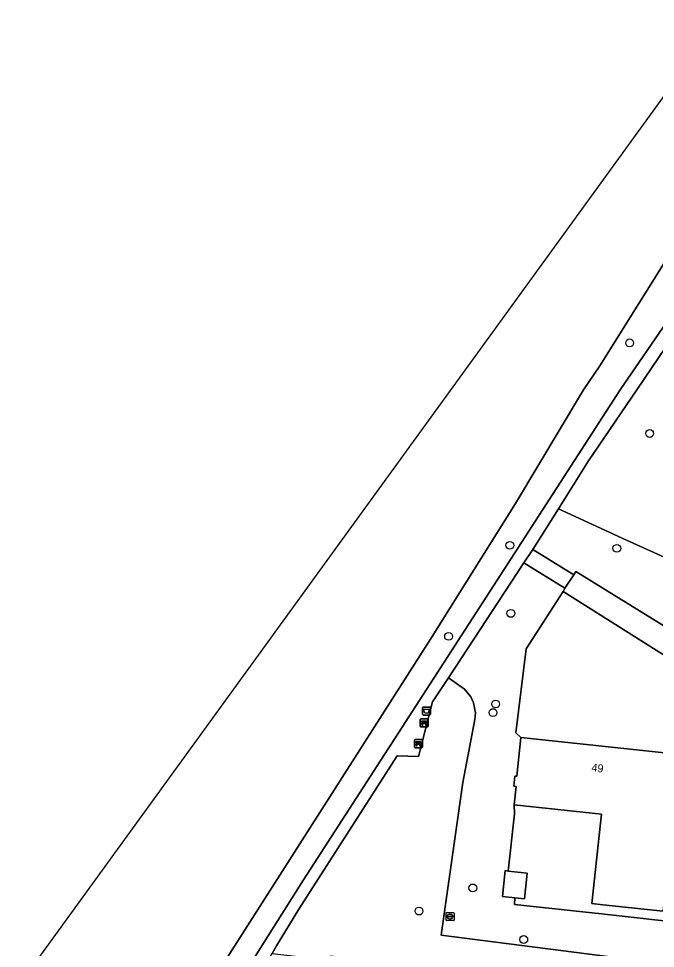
# Model space of a CAD drawing. Extents: x 162396 to 163643, y 386452 to 387406.
# Drawn here: x 162747.7 to 162827.2, y 386930.2 to 387046.4 of the extents above; entities that cross this region are included whole.
import ezdxf

# ---------------------------------------------------------------- set-up
doc = ezdxf.new("R2010")
doc.units = 0
for name, color, linetype in [('IMGEO_Afvalbak', 7, 'Continuous'), ('IMGEO_Bank', 7, 'Continuous'), ('IMGEO_Boom', 7, 'Continuous'), ('IMGEO_Erf', 7, 'Continuous'), ('IMGEO_Groenvoorziening', 7, 'Continuous'), ('IMGEO_Meer_plas_ven_vijver', 7, 'Continuous'), ('IMGEO_Pand', 7, 'Continuous'), ('IMGEO_Pand_nummerreeks', 7, 'Continuous'), ('IMGEO_Rioolput', 7, 'Continuous'), ('IMGEO_Voetpad_halfverhard', 7, 'Continuous'), ('IMGEO_Voetpad_open', 7, 'Continuous')]:
    doc.layers.add(name, color=color, linetype=linetype)

msp = doc.modelspace()

# ---------------------------------------------------------------- linework, layer by layer
at = {"layer": 'IMGEO_Afvalbak'}
for p, q in [((162798.12, 386959.5), (162798.12, 386960.3)), ((162798.12, 386960.3), (162798.12, 386959.5)), ((162798.22, 386960.4), (162799.01, 386960.4)), ((162799.01, 386960.4), (162798.22, 386960.4)), ((162799.11, 386960.3), (162799.11, 386959.5)), ((162799.11, 386959.5), (162799.11, 386960.3)), ((162799.01, 386959.4), (162798.22, 386959.4)), ((162798.22, 386959.4), (162799.01, 386959.4))]:
    msp.add_line(p, q, dxfattribs=at)
msp.add_lwpolyline([(162798.26, 386960.12), (162798.97, 386960.12), (162798.82, 386959.65), (162798.41, 386959.65), (162798.26, 386960.12)], dxfattribs=at)
for centre, start, end in [((162798.22, 386960.3), 90, 180), ((162798.22, 386960.3), 90, 180), ((162799.01, 386960.3), 0, 90), ((162799.01, 386960.3), 360, 90), ((162798.22, 386959.5), 180, 270), ((162798.22, 386959.5), 180, 270), ((162799.01, 386959.5), 270, 0), ((162799.01, 386959.5), 270, 0)]:
    msp.add_arc(centre, 0.1, start, end, dxfattribs=at)
at = {"layer": 'IMGEO_Bank'}
for p, q in [((162797.83, 386957.99), (162797.83, 386958.83)), ((162797.83, 386958.83), (162797.83, 386957.99)), ((162797.91, 386958.91), (162798.75, 386958.91)), ((162798.75, 386958.91), (162797.91, 386958.91)), ((162798.14, 386958.42), (162798.14, 386958.52)), ((162798.18, 386958.52), (162798.18, 386958.42)), ((162798.47, 386958.53), (162798.19, 386958.53)), ((162798.48, 386958.42), (162798.48, 386958.52)), ((162798.52, 386958.52), (162798.52, 386958.42)), ((162798.83, 386958.84), (162798.83, 386958)), ((162798.83, 386958), (162798.83, 386958.84)), ((162798.76, 386957.91), (162797.92, 386957.91)), ((162797.92, 386957.91), (162798.76, 386957.91)), ((162798.53, 386958.31), (162798.14, 386958.31)), ((162798.19, 386958.41), (162798.47, 386958.41)), ((162797.11, 386955.39), (162797.11, 386956.24)), ((162797.11, 386956.24), (162797.11, 386955.39)), ((162797.19, 386956.32), (162798.03, 386956.32)), ((162798.03, 386956.32), (162797.19, 386956.32)), ((162798.11, 386956.25), (162798.11, 386955.4)), ((162798.11, 386955.4), (162798.11, 386956.25)), ((162798.04, 386955.32), (162797.2, 386955.32)), ((162797.2, 386955.32), (162798.04, 386955.32)), ((162797.81, 386955.72), (162797.41, 386955.72)), ((162797.42, 386955.83), (162797.42, 386955.93)), ((162797.46, 386955.93), (162797.46, 386955.83)), ((162797.75, 386955.94), (162797.47, 386955.94)), ((162797.47, 386955.82), (162797.75, 386955.82)), ((162797.76, 386955.83), (162797.76, 386955.93)), ((162797.8, 386955.93), (162797.8, 386955.83))]:
    msp.add_line(p, q, dxfattribs=at)
for points in [[(162798.13, 386958.53), (162798.05, 386958.53), (162798.05, 386958.69), (162798.61, 386958.69), (162798.61, 386958.53), (162798.53, 386958.53)], [(162798.08, 386958.31), (162797.94, 386958.31), (162798.05, 386958.41), (162798.13, 386958.41)], [(162798.13, 386958.3), (162798.13, 386958.09), (162798.09, 386958.09), (162798.09, 386958.3)], [(162798.53, 386958.41), (162798.61, 386958.41), (162798.72, 386958.31), (162798.59, 386958.31)], [(162798.58, 386958.3), (162798.58, 386958.09), (162798.54, 386958.09), (162798.54, 386958.3)], [(162797.36, 386955.72), (162797.22, 386955.72), (162797.33, 386955.82), (162797.41, 386955.82)], [(162797.41, 386955.94), (162797.33, 386955.94), (162797.33, 386956.1), (162797.89, 386956.1), (162797.89, 386955.94), (162797.81, 386955.94)], [(162797.41, 386955.71), (162797.41, 386955.5), (162797.36, 386955.5), (162797.36, 386955.71)], [(162797.81, 386955.82), (162797.89, 386955.82), (162798, 386955.72), (162797.86, 386955.72)], [(162797.86, 386955.71), (162797.86, 386955.5), (162797.81, 386955.5), (162797.81, 386955.71)]]:
    msp.add_lwpolyline(points, dxfattribs=at)
for centre, radius, start, end in [((162797.91, 386958.83), 0.0779, 92.4484, 184.2845), ((162797.91, 386958.83), 0.0779, 92.4484, 184.2845), ((162798.13, 386958.52), 0.00671, 2.8957, 87.1043), ((162798.19, 386958.52), 0.00671, 92.8957, 177.1043), ((162798.47, 386958.52), 0.00671, 2.8957, 87.1043), ((162798.53, 386958.52), 0.00671, 92.8957, 177.1043), ((162798.75, 386958.83), 0.0779, 2.4484, 94.2845), ((162798.75, 386958.83), 0.0779, 2.4484, 94.2845), ((162797.91, 386957.99), 0.0779, 182.4484, 274.2845), ((162797.91, 386957.99), 0.0779, 182.4484, 274.2845), ((162798.08, 386958.3), 0.00671, 2.8957, 87.1043), ((162798.13, 386958.42), 0.00671, 272.8957, 357.1043), ((162798.14, 386958.3), 0.00671, 92.8957, 177.1043), ((162798.19, 386958.42), 0.00671, 182.8957, 267.1043), ((162798.47, 386958.42), 0.00671, 272.8957, 357.1043), ((162798.53, 386958.42), 0.00671, 182.8957, 267.1043), ((162798.53, 386958.3), 0.00671, 2.8957, 87.1043), ((162798.59, 386958.3), 0.00671, 92.8957, 177.1043), ((162798.75, 386957.99), 0.0779, 272.4484, 4.2845), ((162798.75, 386957.99), 0.0779, 272.4484, 4.2845), ((162797.19, 386956.24), 0.0779, 92.4484, 184.2845), ((162797.19, 386956.24), 0.0779, 92.4484, 184.2845), ((162798.03, 386956.24), 0.0779, 2.4484, 94.2845), ((162798.03, 386956.24), 0.0779, 2.4484, 94.2845), ((162797.19, 386955.4), 0.0779, 182.4484, 274.2845), ((162797.19, 386955.4), 0.0779, 182.4484, 274.2845), ((162797.36, 386955.71), 0.00671, 2.8957, 87.1043), ((162797.41, 386955.93), 0.00671, 2.8957, 87.1043), ((162797.41, 386955.83), 0.00671, 272.8957, 357.1043), ((162797.42, 386955.71), 0.00671, 92.8957, 177.1043), ((162797.47, 386955.93), 0.00671, 92.8957, 177.1043), ((162797.47, 386955.83), 0.00671, 182.8957, 267.1043), ((162797.75, 386955.93), 0.00671, 2.8957, 87.1043), ((162797.75, 386955.83), 0.00671, 272.8957, 357.1043), ((162797.81, 386955.93), 0.00671, 92.8957, 177.1043), ((162797.81, 386955.83), 0.00671, 182.8957, 267.1043), ((162797.81, 386955.71), 0.00671, 2.8957, 87.1043), ((162797.86, 386955.71), 0.00671, 92.8957, 177.1043), ((162798.03, 386955.4), 0.0779, 272.4484, 4.2845), ((162798.03, 386955.4), 0.0779, 272.4484, 4.2845)]:
    msp.add_arc(centre, radius, start, end, dxfattribs=at)
at = {"layer": 'IMGEO_Boom'}
for centre in [(162823.99, 387005.88), (162826.48, 386994.57), (162809.02, 386980.6), (162822.39, 386980.22), (162809.16, 386972.09), (162801.38, 386969.22), (162807.26, 386960.78), (162806.92, 386959.7), (162804.4, 386937.8), (162797.68, 386934.91), (162810.76, 386931.36)]:
    msp.add_circle(centre, 0.489, dxfattribs=at)
at = {"layer": 'IMGEO_Erf'}
for points in [[(162831.57, 386964.81), (162815.68, 386974.83), (162811.08, 386967.66), (162809.79, 386957.16), (162810.4, 386956.6), (162830.3, 386954.46)], [(162828.17, 386934.88), (162820.65, 386935.69), (162819.27, 386935.84), (162820.35, 386945.9), (162820.47, 386947.02), (162809.55, 386948.19), (162809.62, 386947.04), (162808.83, 386939.91), (162811.19, 386939.66), (162810.84, 386936.43), (162809.66, 386936.56), (162809.62, 386935.74), (162820.48, 386934.56), (162828.24, 386933.71)]]:
    msp.add_lwpolyline(points, dxfattribs=at)
at = {"layer": 'IMGEO_Groenvoorziening'}
for points in [[(162822.79, 387000), (162840.21, 387025.39), (162850.89, 387039.17), (162851.19, 387040.6), (162851.15, 387042.93), (162848.38, 387044.77), (162846.89, 387045.9), (162844.23, 387041.73), (162841.3, 387036.72), (162834.64, 387026.06), (162820.24, 387003), (162818.24, 387000.01), (162809.72, 386985.81), (162799.34, 386969.19), (162769.37, 386922.25), (162756.79, 386901.93), (162764.1, 386897.03), (162767.1, 386909.87), (162773.1, 386921.91), (162776.86, 386928.66), (162783.25, 386938.8)], [(162815.1, 386985.16), (162811.9, 386980.07), (162817.03, 386976.92), (162817.25, 386977.34), (162828.23, 386970.53), (162829.12, 386974.33), (162829.12, 386977.33), (162829.12, 386978.76), (162823.57, 386981.26)]]:
    msp.add_lwpolyline(points, close=True, dxfattribs=at)
for points in [[(162837.53, 387018.71), (162824.9, 387000), (162818.86, 386991.15), (162815.1, 386985.16), (162823.57, 386981.26), (162829.12, 386978.76)], [(162828.24, 386933.71), (162820.48, 386934.56), (162809.62, 386935.74), (162809.66, 386936.56), (162808.1, 386936.73), (162808.44, 386939.96), (162808.83, 386939.91), (162809.62, 386947.04), (162809.55, 386948.19), (162809.8, 386950.48), (162809.52, 386950.51), (162809.65, 386951.77), (162809.88, 386951.75), (162810.4, 386956.6), (162809.79, 386957.16), (162811.08, 386967.66), (162815.68, 386974.83), (162815.91, 386975.23), (162810.79, 386978.39), (162801.36, 386964.04), (162803.37, 386962.61), (162804.16, 386961.67), (162804.51, 386960.91), (162804.74, 386959.67), (162804.67, 386958.84), (162803.17, 386950.96), (162800.47, 386931.89), (162828.69, 386928.27)], [(162828.69, 386928.27), (162800.47, 386931.89), (162803.17, 386950.96), (162804.67, 386958.84), (162804.74, 386959.67), (162804.51, 386960.91), (162804.16, 386961.67), (162803.37, 386962.61), (162801.36, 386964.04), (162799.38, 386961.03), (162797.63, 386954.22), (162794.98, 386954.29), (162782.7, 386935.15), (162779.88, 386930.58), (162779.36, 386929.62), (162786.56, 386928.76), (162786.64, 386929.32), (162812.5, 386926.45), (162811.66, 386918.95), (162813.64, 386916.29), (162827.93, 386914.73)]]:
    msp.add_lwpolyline(points, dxfattribs=at)
at = {"layer": 'IMGEO_Meer_plas_ven_vijver'}
msp.add_lwpolyline([(162918.38, 387161.06), (162747.7, 386925.61), (162748.57, 386924.87), (162750.53, 386923.54), (162758.68, 386919.38), (162759.44, 386919.08), (162760.21, 386918.86), (162761.01, 386918.7), (162761.81, 386918.61), (162762.52, 386918.6), (162763.33, 386918.64), (162764.13, 386918.77), (162764.92, 386918.96), (162765.69, 386919.22), (162766.43, 386919.55), (162766.85, 386919.78), (162768.07, 386920.61), (162769.37, 386922.25), (162799.34, 386969.19), (162809.72, 386985.81), (162818.24, 387000.01), (162820.24, 387003), (162834.64, 387026.06)], dxfattribs=at)
at = {"layer": 'IMGEO_Pand'}
for points in [[(162809.55, 386948.19), (162820.47, 386947.02), (162820.35, 386945.9), (162819.27, 386935.84), (162820.65, 386935.69), (162828.17, 386934.88), (162828.71, 386939.85), (162829.52, 386947.34), (162830.2, 386953.55), (162830.3, 386954.46), (162810.4, 386956.6), (162809.88, 386951.75), (162809.65, 386951.77), (162809.52, 386950.51), (162809.8, 386950.48)], [(162808.83, 386939.91), (162808.44, 386939.96), (162808.1, 386936.73), (162809.66, 386936.56), (162810.84, 386936.43), (162811.19, 386939.66)]]:
    msp.add_lwpolyline(points, close=True, dxfattribs=at)
at = {"layer": 'IMGEO_Rioolput'}
for p, q in [((162801.06, 386933.79), (162801.06, 386934.65)), ((162801.14, 386934.72), (162801.99, 386934.72)), ((162801.32, 386934.21), (162801.32, 386934.23)), ((162801.76, 386934.18), (162801.36, 386934.18)), ((162801.37, 386934.26), (162801.76, 386934.26)), ((162801.55, 386934.5), (162801.58, 386934.5)), ((162801.81, 386934.23), (162801.81, 386934.21)), ((162802.06, 386934.65), (162802.06, 386933.79)), ((162801.99, 386933.72), (162801.14, 386933.72)), ((162801.57, 386933.94), (162801.55, 386933.94))]:
    msp.add_line(p, q, dxfattribs=at)
for points in [[(162801.06, 386933.79), (162801.06, 386934.65)], [(162801.14, 386934.72), (162801.99, 386934.72)], [(162802.06, 386934.65), (162802.06, 386933.79)], [(162801.99, 386933.72), (162801.14, 386933.72)]]:
    msp.add_lwpolyline(points, dxfattribs=at)
for centre, radius, start, end in [((162801.14, 386934.64), 0.0765, 91.552, 178.448), ((162801.14, 386934.64), 0.0765, 91.552, 178.448), ((162801.36, 386934.22), 0.0403, 85.8775, 175.7526), ((162801.36, 386934.21), 0.0366, 178.938, 274.7102), ((162801.77, 386934.22), 0.0386, 1.7309, 96.639), ((162801.76, 386934.22), 0.043, 264.8664, 352.4533), ((162801.99, 386934.64), 0.0765, 1.552, 88.448), ((162801.99, 386934.64), 0.0765, 1.552, 88.448), ((162801.14, 386933.79), 0.0765, 181.552, 268.448), ((162801.14, 386933.79), 0.0765, 181.552, 268.448), ((162801.99, 386933.79), 0.0765, 271.552, 358.448), ((162801.99, 386933.79), 0.0765, 271.552, 358.448)]:
    msp.add_arc(centre, radius, start, end, dxfattribs=at)
for centre, major_axis, ratio, start_param, end_param in [((162801.55, 386934.22), (-0.387, 0.002), 0.722429, 4.712389, 7.853982), ((162801.57, 386934.22), (-0.39, 0.002), 0.717154, 1.570796, 4.712389)]:
    msp.add_ellipse(centre, major_axis=major_axis, ratio=ratio, start_param=start_param, end_param=end_param, dxfattribs=at)
at = {"layer": 'IMGEO_Voetpad_halfverhard'}
for points in [[(162824.9, 387000), (162837.53, 387018.71), (162838.27, 387018.23), (162842.2, 387023.96), (162841.49, 387024.49), (162851.71, 387037.61)], [(162840.21, 387025.39), (162822.79, 387000), (162783.25, 386938.8), (162776.86, 386928.66), (162773.1, 386921.91), (162767.1, 386909.87), (162764.1, 386897.03), (162765.73, 386895.99), (162768.62, 386909.52), (162774.58, 386921.34), (162777.16, 386925.94), (162777.97, 386927.26), (162779.36, 386929.62), (162779.88, 386930.58), (162782.7, 386935.15), (162794.98, 386954.29), (162797.63, 386954.22), (162799.38, 386961.03), (162801.36, 386964.04), (162810.79, 386978.39), (162811.9, 386980.07), (162815.1, 386985.16), (162818.86, 386991.15), (162824.9, 387000)]]:
    msp.add_lwpolyline(points, dxfattribs=at)
at = {"layer": 'IMGEO_Voetpad_open'}
msp.add_lwpolyline([(162811.9, 386980.07), (162810.79, 386978.39), (162815.91, 386975.23), (162817.03, 386976.92)], close=True, dxfattribs=at)
msp.add_lwpolyline([(162828.23, 386970.53), (162817.25, 386977.34), (162817.03, 386976.92), (162815.91, 386975.23), (162815.68, 386974.83), (162831.57, 386964.81), (162831.24, 386961.41), (162873.94, 386956.55), (162882.09, 386955.73), (162882.13, 386956.01), (162886.65, 386955.5), (162886.61, 386955.23), (162896.53, 386954.06)], dxfattribs=at)

# ---------------------------------------------------------------- texts
at = {"layer": 'IMGEO_Pand_nummerreeks'}
msp.add_text('49', height=1, rotation=353.8627, dxfattribs=at).set_placement((162819.18, 386952.36))

doc.saveas('drawing.dxf')
